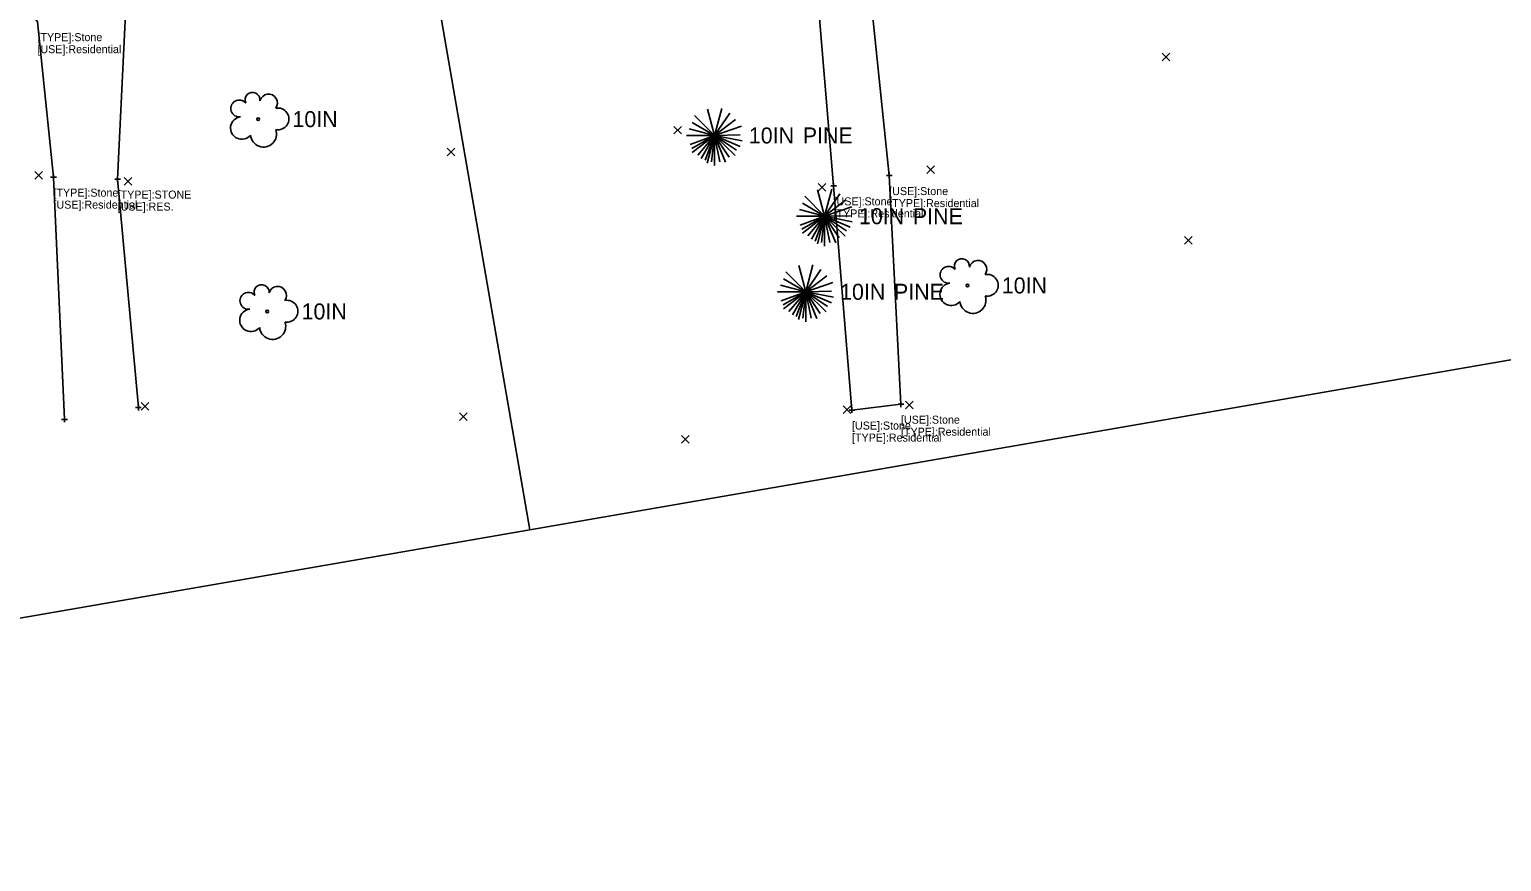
# Model space of a CAD drawing. Extents: x 1386013 to 1389776, y 604170 to 607009.
# Drawn here: x 1386970 to 1387227.5, y 604555.8 to 604701.4 of the extents above; entities that cross this region are included whole.
import ezdxf

# ---------------------------------------------------------------- set-up
doc = ezdxf.new("R2010")
doc.units = 0
for name, color, linetype in [('_CIVIL_CONSTRUCTION', 7, 'Continuous'), ('DV_X_Text', 7, 'Continuous'), ('PV_X_Driveway', 7, 'Continuous'), ('SH_Cut_Line', 7, 'Continuous'), ('SV_X_Random_Point', 7, 'Continuous'), ('SV_X_Text', 7, 'Continuous'), ('VG_X_Text', 7, 'Continuous')]:
    doc.layers.add(name, color=color, linetype=linetype)

msp = doc.modelspace()

# ---------------------------------------------------------------- linework, layer by layer
at = {"layer": '_CIVIL_CONSTRUCTION'}
for p, q in [((1387089.86, 604682.81), (1387086.37, 604686.29)), ((1387089.86, 604682.81), (1387088.63, 604687.42)), ((1387089.86, 604682.81), (1387091.12, 604687.5)), ((1387089.86, 604682.81), (1387092.52, 604686.69)), ((1387089.86, 604682.81), (1387085.45, 604683.99)), ((1387089.86, 604682.81), (1387085.96, 604685.1)), ((1387089.86, 604682.81), (1387093.52, 604685.61)), ((1387089.86, 604682.81), (1387094.6, 604684.41)), ((1387084.93, 604682.81), (1387089.86, 604682.81)), ((1387089.86, 604682.81), (1387085.57, 604681.24)), ((1387089.86, 604682.81), (1387085.88, 604680.52)), ((1387089.86, 604682.81), (1387085.96, 604679.81)), ((1387089.86, 604682.81), (1387086.92, 604679.34)), ((1387089.86, 604682.81), (1387087.55, 604678.79)), ((1387089.86, 604682.81), (1387088.2, 604678.47)), ((1387089.86, 604682.81), (1387088.6, 604677.95)), ((1387089.86, 604682.81), (1387089.32, 604678.21)), ((1387089.86, 604682.81), (1387094.37, 604682.9)), ((1387089.86, 604677.57), (1387089.86, 604682.81)), ((1387089.86, 604682.81), (1387090.79, 604678.17)), ((1387089.86, 604682.81), (1387091.8, 604678.14)), ((1387089.86, 604682.81), (1387092.4, 604679.01)), ((1387089.86, 604682.81), (1387093.45, 604679.28)), ((1387089.86, 604682.81), (1387093.69, 604680.25)), ((1387089.86, 604682.81), (1387094.33, 604680.86)), ((1387089.86, 604682.81), (1387094.69, 604681.85)), ((1387109.12, 604668.69), (1387110.38, 604673.39)), ((1387109.12, 604668.69), (1387105.22, 604670.99)), ((1387109.12, 604668.69), (1387105.63, 604672.18)), ((1387109.12, 604668.69), (1387107.89, 604673.31)), ((1387109.12, 604668.69), (1387111.78, 604672.58)), ((1387109.12, 604668.69), (1387112.78, 604671.5)), ((1387104.19, 604668.69), (1387109.12, 604668.69)), ((1387109.12, 604668.69), (1387104.71, 604669.88)), ((1387109.12, 604668.69), (1387104.83, 604667.13)), ((1387109.12, 604668.69), (1387105.14, 604666.41)), ((1387109.12, 604668.69), (1387105.22, 604665.7)), ((1387109.12, 604668.69), (1387106.18, 604665.23)), ((1387109.12, 604668.69), (1387106.8, 604664.68)), ((1387109.12, 604668.69), (1387107.46, 604664.35)), ((1387109.12, 604668.69), (1387107.86, 604663.84)), ((1387109.12, 604668.69), (1387108.58, 604664.1)), ((1387109.12, 604668.69), (1387113.86, 604670.3)), ((1387109.12, 604668.69), (1387113.63, 604668.78)), ((1387109.12, 604663.45), (1387109.12, 604668.69)), ((1387109.12, 604668.69), (1387110.04, 604664.06)), ((1387109.12, 604668.69), (1387111.06, 604664.02)), ((1387109.12, 604668.69), (1387111.66, 604664.9)), ((1387109.12, 604668.69), (1387112.71, 604665.17)), ((1387109.12, 604668.69), (1387112.94, 604666.14)), ((1387109.12, 604668.69), (1387113.59, 604666.75)), ((1387109.12, 604668.69), (1387113.95, 604667.73)), ((1387105.82, 604655.47), (1387102.33, 604658.95)), ((1387105.82, 604655.47), (1387104.59, 604660.08)), ((1387105.82, 604655.47), (1387107.08, 604660.17)), ((1387105.82, 604655.47), (1387108.48, 604659.35)), ((1387105.82, 604655.47), (1387109.48, 604658.27)), ((1387100.89, 604655.47), (1387105.82, 604655.47)), ((1387105.82, 604655.47), (1387101.41, 604656.65)), ((1387105.82, 604655.47), (1387101.53, 604653.91)), ((1387105.82, 604655.47), (1387101.84, 604653.19)), ((1387105.82, 604655.47), (1387101.92, 604657.76)), ((1387105.82, 604655.47), (1387101.92, 604652.47)), ((1387105.82, 604655.47), (1387102.88, 604652)), ((1387105.82, 604655.47), (1387103.5, 604651.45)), ((1387105.82, 604655.47), (1387104.16, 604651.13)), ((1387105.82, 604655.47), (1387104.56, 604650.61)), ((1387105.82, 604655.47), (1387105.28, 604650.88)), ((1387105.82, 604655.47), (1387110.56, 604657.07)), ((1387105.82, 604655.47), (1387110.33, 604655.56)), ((1387105.82, 604650.23), (1387105.82, 604655.47)), ((1387105.82, 604655.47), (1387106.74, 604650.83)), ((1387105.82, 604655.47), (1387107.76, 604650.8)), ((1387105.82, 604655.47), (1387108.36, 604651.67)), ((1387105.82, 604655.47), (1387109.41, 604651.95)), ((1387105.82, 604655.47), (1387109.64, 604652.91)), ((1387105.82, 604655.47), (1387110.29, 604653.53)), ((1387105.82, 604655.47), (1387110.65, 604654.51))]:
    msp.add_line(p, q, dxfattribs=at)
for centre in [(1387010.04, 604685.66), (1387134.1, 604656.58), (1387011.64, 604652.03)]:
    msp.add_circle(centre, 0.24, dxfattribs=at)
for centre, radius, start, end in [((1387006.73, 604687.53), 1.47, 39.0625, 279.5412), ((1387009.05, 604689.03), 1.32, 354.0047, 205.9741), ((1387011.86, 604688.49), 1.55, 323.83, 165.0376), ((1387013.5, 604685.7), 1.91, 259.1453, 101.4596), ((1387007.18, 604684.11), 1.97, 96.1722, 320.5737), ((1387010.98, 604683.06), 2.28, 184.9476, 19.4572), ((1387133.12, 604659.94), 1.32, 354.0047, 205.9741), ((1387135.93, 604659.4), 1.55, 323.83, 165.0376), ((1387130.79, 604658.44), 1.47, 39.0625, 279.5412), ((1387137.56, 604656.61), 1.91, 259.1453, 101.4596), ((1387008.33, 604653.89), 1.47, 39.0625, 279.5412), ((1387010.65, 604655.4), 1.32, 354.0047, 205.9741), ((1387013.46, 604654.86), 1.55, 323.83, 165.0376), ((1387131.25, 604655.03), 1.97, 96.1722, 320.5737), ((1387015.1, 604652.07), 1.91, 259.1453, 101.4596), ((1387135.05, 604653.97), 2.28, 184.9476, 19.4572), ((1387008.78, 604650.48), 1.97, 96.1722, 320.5737), ((1387012.58, 604649.42), 2.28, 184.9476, 19.4572)]:
    msp.add_arc(centre, radius, start, end, dxfattribs=at)
at = {"layer": 'DV_X_Text'}
for p, q in [((1386974.25, 604676.01), (1386974.25, 604675.01)), ((1387120.41, 604676.28), (1387120.41, 604675.28)), ((1386973.75, 604675.51), (1386974.75, 604675.51)), ((1386974.25, 604675.51), (1386974.25, 604675.51)), ((1386984.97, 604675.17), (1386985.97, 604675.17)), ((1386985.47, 604675.67), (1386985.47, 604674.67)), ((1386985.47, 604675.17), (1386985.47, 604675.17)), ((1387110.18, 604673.98), (1387111.18, 604673.98)), ((1387110.68, 604674.48), (1387110.68, 604673.48)), ((1387110.68, 604673.98), (1387110.68, 604673.98)), ((1387119.91, 604675.78), (1387120.91, 604675.78)), ((1387120.41, 604675.78), (1387120.41, 604675.78)), ((1386988.59, 604635.22), (1386989.59, 604635.22)), ((1386989.09, 604635.72), (1386989.09, 604634.72)), ((1386989.09, 604635.22), (1386989.09, 604635.22)), ((1387113.4, 604634.77), (1387114.4, 604634.77)), ((1387113.9, 604635.27), (1387113.9, 604634.27)), ((1387113.9, 604634.77), (1387113.9, 604634.77)), ((1387121.97, 604635.8), (1387122.97, 604635.8)), ((1387122.47, 604636.3), (1387122.47, 604635.3)), ((1387122.47, 604635.8), (1387122.47, 604635.8)), ((1386975.67, 604633.16), (1386976.67, 604633.16)), ((1386976.17, 604633.66), (1386976.17, 604632.66)), ((1386976.17, 604633.16), (1386976.17, 604633.16))]:
    msp.add_line(p, q, dxfattribs=at)
at = {"layer": 'PV_X_Driveway'}
for points in [[(1387118.13, 604745.05), (1387117.46, 604729.83), (1387116.74, 604711.35), (1387120.41, 604675.78), (1387122.47, 604635.8), (1387113.9, 604634.77), (1387110.68, 604673.98), (1387107.5, 604711.74), (1387104.46, 604731.4), (1387098.22, 604730.8), (1387096.82, 604742.49)], [(1386989.09, 604635.22), (1386985.47, 604675.17), (1386987.16, 604710.17), (1386991.17, 604725.17)], [(1386976.17, 604633.16), (1386974.25, 604675.51), (1386971.44, 604702.7), (1386967.09, 604708.68), (1386964.42, 604718.9)]]:
    msp.add_lwpolyline(points, dxfattribs=at)
at = {"layer": 'SH_Cut_Line'}
for points in [[(1387057.58, 604613.85), (1387020.03, 604830.63), (1387355.04, 604888.66), (1387392.59, 604671.89)], [(1386722.57, 604555.82), (1386685.02, 604772.59), (1387020.03, 604830.63), (1387057.58, 604613.85)]]:
    msp.add_lwpolyline(points, close=True, dxfattribs=at)
at = {"layer": 'SV_X_Random_Point'}
for p, q in [((1387168.17, 604695.86), (1387169.5, 604697.2)), ((1387168.17, 604697.2), (1387169.5, 604695.86)), ((1387082.73, 604683.07), (1387084.07, 604684.4)), ((1387082.73, 604684.4), (1387084.07, 604683.07)), ((1387043.12, 604679.27), (1387044.45, 604680.6)), ((1387043.12, 604680.6), (1387044.45, 604679.27)), ((1386970.98, 604675.15), (1386972.32, 604676.49)), ((1386970.98, 604676.49), (1386972.32, 604675.15)), ((1387126.97, 604676.16), (1387128.31, 604677.49)), ((1387126.97, 604677.49), (1387128.31, 604676.16)), ((1386986.63, 604674.12), (1386987.97, 604675.46)), ((1386986.63, 604675.46), (1386987.97, 604674.12)), ((1387108.01, 604673.07), (1387109.34, 604674.4)), ((1387108.01, 604674.4), (1387109.34, 604673.07)), ((1387172.06, 604663.8), (1387173.4, 604665.14)), ((1387172.06, 604665.14), (1387173.4, 604663.8)), ((1386989.57, 604634.74), (1386990.9, 604636.08)), ((1386989.57, 604636.08), (1386990.9, 604634.74)), ((1387112.37, 604634.17), (1387113.7, 604635.51)), ((1387112.37, 604635.51), (1387113.7, 604634.17)), ((1387123.27, 604635.01), (1387124.6, 604636.35)), ((1387123.27, 604636.35), (1387124.6, 604635.01)), ((1387045.24, 604632.94), (1387046.57, 604634.27)), ((1387045.24, 604634.27), (1387046.57, 604632.94)), ((1387084.09, 604628.99), (1387085.42, 604630.33)), ((1387084.09, 604630.33), (1387085.42, 604628.99))]:
    msp.add_line(p, q, dxfattribs=at)

# ---------------------------------------------------------------- texts
at = {"layer": 'SV_X_Text'}
for s, p in [('[TYPE]:Stone', (1386971.44, 604699.3)), ('[USE]:Residential', (1386971.44, 604697.2)), ('[TYPE]:Stone', (1386974.25, 604672.11)), ('[USE]:Stone', (1387120.41, 604672.38)), ('[USE]:Residential', (1386974.25, 604670.01)), ('[TYPE]:STONE', (1386985.47, 604671.77)), ('[USE]:RES.', (1386985.47, 604669.67)), ('[USE]:Stone', (1387110.68, 604670.58)), ('[TYPE]:Residential', (1387120.41, 604670.28)), ('[TYPE]:Residential', (1387110.68, 604668.48)), ('[USE]:Stone', (1387113.9, 604631.37)), ('[USE]:Stone', (1387122.47, 604632.4)), ('[TYPE]:Residential', (1387113.9, 604629.27)), ('[TYPE]:Residential', (1387122.47, 604630.3))]:
    msp.add_text(s, height=1.4, dxfattribs=at).set_placement(p)
at = {"layer": 'VG_X_Text'}
for s, p in [('10IN', (1387016.04, 604684.26)), ('10IN', (1387095.86, 604681.41)), ('PINE', (1387105.29, 604681.41)), ('10IN', (1387115.12, 604667.29)), ('PINE', (1387124.55, 604667.29)), ('10IN', (1387140.1, 604655.18)), ('10IN', (1387111.82, 604654.07)), ('PINE', (1387121.24, 604654.07)), ('10IN', (1387017.64, 604650.63))]:
    msp.add_text(s, height=2.8, dxfattribs=at).set_placement(p)

doc.saveas('drawing.dxf')
